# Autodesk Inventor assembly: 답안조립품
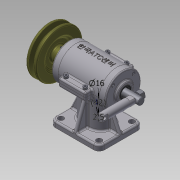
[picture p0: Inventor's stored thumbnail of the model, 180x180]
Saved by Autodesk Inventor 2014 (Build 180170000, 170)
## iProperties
Created: 2015-05
Part Number: 답안조립품
Document SubType Name: Assembly
Designer: Administrator
Author: Administrator
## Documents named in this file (18)
- C:\Documents and Settings\Administrator\바탕 화면\350508V1012\답안조립품.iam
- C:\Documents and Settings\Administrator\바탕 화면\350508V1012\스프링.ipt
- C:\Documents and Settings\Administrator\바탕 화면\350508V1012\본체.ipt
- C:\Documents and Settings\Administrator\바탕 화면\350508V1012\본체 커버.ipt
- C:\Documents and Settings\Administrator\바탕 화면\350508V1012\M4x0.5x14.ipt
- C:\Documents and Settings\Administrator\바탕 화면\350508V1012\앞커버.ipt
- C:\Documents and Settings\Administrator\바탕 화면\350508V1012\뒤커버.ipt
- C:\Documents and Settings\Administrator\바탕 화면\350508V1012\M3x0.5x8.ipt
- C:\Documents and Settings\Administrator\바탕 화면\350508V1012\편심축.ipt
- C:\Documents and Settings\Administrator\바탕 화면\350508V1012\베어링 6201.ipt
- C:\Documents and Settings\Administrator\바탕 화면\350508V1012\베어링 6202.ipt
- C:\Documents and Settings\Administrator\바탕 화면\350508V1012\오일실.ipt
- C:\Documents and Settings\Administrator\바탕 화면\350508V1012\키4x4.ipt
- C:\Documents and Settings\Administrator\바탕 화면\350508V1012\V-벨트풀리.ipt
- C:\Documents and Settings\Administrator\바탕 화면\350508V1012\멈춤나사.ipt
- C:\Documents and Settings\Administrator\바탕 화면\350508V1012\링크.ipt
- C:\Documents and Settings\Administrator\바탕 화면\350508V1012\너트 M8.ipt
- C:\Documents and Settings\Administrator\바탕 화면\350508V1012\슬라이드.ipt
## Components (14 placed, 4 different names)
1. M4x0.5x14:1
2. M4x0.5x14:2
3. M4x0.5x14:3
4. M4x0.5x14:4
5. V-벨트풀리:1 — 플러쉬:1, 구동부
6. KS B 1012 C - 미터 C M8:1
7. M3x0.5x8:1
8. M3x0.5x8:3
9. M3x0.5x8:4
10. M3x0.5x8:5
11. M3x0.5x8:2
12. M3x0.5x8:6
13. M3x0.5x8:7
14. M3x0.5x8:8
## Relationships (2: Flush 1, Angle 1)
- 플러쉬:1 [Flush]: V-벨트풀리:1
- 구동부 [Angle]: V-벨트풀리:1
